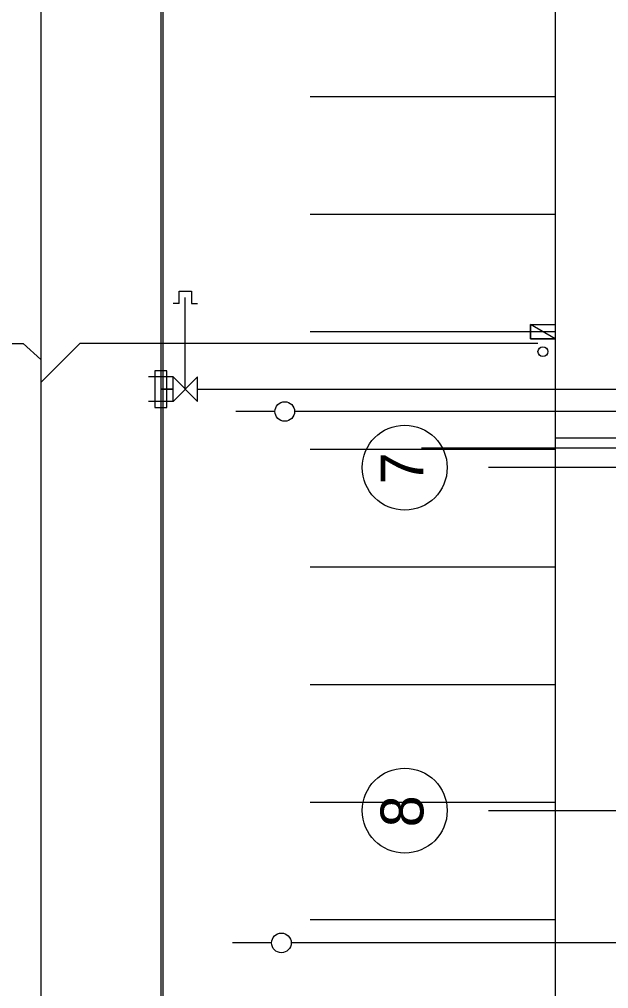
# Model space of a CAD drawing. Extents: x -264205 to -263659, y -1242401 to -1242060.
# Drawn here: x -263927.03 to -263915, y -1242129.52 to -1242109.73 of the extents above; entities that cross this region are included whole.
import ezdxf

# ---------------------------------------------------------------- set-up
doc = ezdxf.new("R2010")
doc.units = 0
for name, color, linetype in [('OSI_STAVBY_KFA', 7, 'Continuous'), ('SITUACIA_DSP_2D', 7, 'Continuous'), ('TDZ_VODOROVNE_PROJEKT', 7, 'Continuous')]:
    doc.layers.add(name, color=color, linetype=linetype)

msp = doc.modelspace()

# ---------------------------------------------------------------- linework, layer by layer
at = {"layer": 'OSI_STAVBY_KFA'}
for p, q in [((-263792.653, -1242118.882), (-263917.453, -1242118.882)), ((-263917.453, -1242125.882), (-263905.505, -1242125.882)), ((-263917.453, -1242125.882), (-263905.505, -1242125.882))]:
    msp.add_line(p, q, dxfattribs=at)
for centre in [(-263919.163, -1242118.883), (-263919.163, -1242125.883)]:
    msp.add_circle(centre, 0.867, dxfattribs=at)
at = {"layer": 'SITUACIA_DSP_2D'}
for p, q in [((-263924.143, -1242082.64), (-263924.143, -1242185.14)), ((-263926.593, -1242107.902), (-263926.593, -1242154.252)), ((-263926.593, -1242107.902), (-263926.593, -1242154.252)), ((-263923.768, -1242115.532), (-263923.768, -1242115.282)), ((-263923.768, -1242115.282), (-263923.518, -1242115.282)), ((-263923.518, -1242115.282), (-263923.518, -1242115.532)), ((-263923.768, -1242115.532), (-263923.893, -1242115.532)), ((-263923.643, -1242117.282), (-263923.643, -1242115.407)), ((-263923.518, -1242115.532), (-263923.393, -1242115.532)), ((-263916.593, -1242116.252), (-263916.593, -1242115.962)), ((-263916.593, -1242115.962), (-263916.093, -1242115.962)), ((-263916.093, -1242116.252), (-263916.593, -1242115.962)), ((-263916.093, -1242116.252), (-263916.593, -1242115.962)), ((-263916.593, -1242115.962), (-263916.593, -1242116.252)), ((-263916.093, -1242115.962), (-263916.093, -1242116.252)), ((-263936.743, -1242116.352), (-263926.953, -1242116.352)), ((-263926.953, -1242116.352), (-263926.592, -1242116.677)), ((-263925.797, -1242116.352), (-263926.592, -1242117.147)), ((-263916.443, -1242116.352), (-263925.797, -1242116.352)), ((-263916.093, -1242116.252), (-263916.593, -1242116.252)), ((-263916.593, -1242116.252), (-263916.093, -1242116.252)), ((-263924.018, -1242116.907), (-263924.268, -1242116.907)), ((-263924.268, -1242116.907), (-263924.268, -1242117.657)), ((-263924.018, -1242117.657), (-263924.018, -1242116.907)), ((-263923.893, -1242117.032), (-263924.393, -1242117.032)), ((-263923.893, -1242117.532), (-263923.893, -1242117.032)), ((-263923.893, -1242117.032), (-263923.393, -1242117.532)), ((-263923.393, -1242117.032), (-263923.893, -1242117.532)), ((-263923.393, -1242117.532), (-263923.393, -1242117.032)), ((-263924.143, -1242117.282), (-263923.893, -1242117.282)), ((-263923.893, -1242117.282), (-263924.143, -1242117.282)), ((-263923.393, -1242117.282), (-263906.493, -1242117.282)), ((-263923.893, -1242117.532), (-263924.393, -1242117.532)), ((-263924.268, -1242117.657), (-263924.018, -1242117.657)), ((-263921.812, -1242117.737), (-263922.612, -1242117.737)), ((-263903.343, -1242117.732), (-263921.412, -1242117.737)), ((-263893.618, -1242118.282), (-263916.093, -1242118.282)), ((-263916.093, -1242118.282), (-263916.093, -1242175.482)), ((-263908.718, -1242118.482), (-263918.819, -1242118.482)), ((-263921.881, -1242128.582), (-263922.681, -1242128.582)), ((-263917.093, -1242128.582), (-263921.481, -1242128.582)), ((-263909.043, -1242128.582), (-263917.093, -1242128.582))]:
    msp.add_line(p, q, dxfattribs=at)
for centre, radius in [((-263916.343, -1242116.514), 0.1), ((-263921.612, -1242117.737), 0.2), ((-263921.681, -1242128.582), 0.2)]:
    msp.add_circle(centre, radius, dxfattribs=at)
at = {"layer": 'TDZ_VODOROVNE_PROJEKT'}
for p, q in [((-263924.088, -1242241.458), (-263924.093, -1242087.307)), ((-263916.093, -1242087.308), (-263916.093, -1242141.207)), ((-263921.093, -1242111.307), (-263916.093, -1242111.307)), ((-263921.093, -1242113.707), (-263916.093, -1242113.707)), ((-263921.093, -1242116.107), (-263916.093, -1242116.107)), ((-263921.093, -1242118.507), (-263916.093, -1242118.507)), ((-263921.093, -1242120.907), (-263916.093, -1242120.907)), ((-263921.093, -1242123.307), (-263916.093, -1242123.307)), ((-263921.093, -1242125.707), (-263916.093, -1242125.707)), ((-263921.093, -1242128.107), (-263916.093, -1242128.107))]:
    msp.add_line(p, q, dxfattribs=at)

# ---------------------------------------------------------------- texts
at = {"layer": 'OSI_STAVBY_KFA'}
for s, p in [('7', (-263918.782, -1242119.223)), ('8', (-263918.782, -1242126.223))]:
    msp.add_text(s, height=0.875, rotation=90, dxfattribs=at).set_placement(p)

doc.saveas('drawing.dxf')
